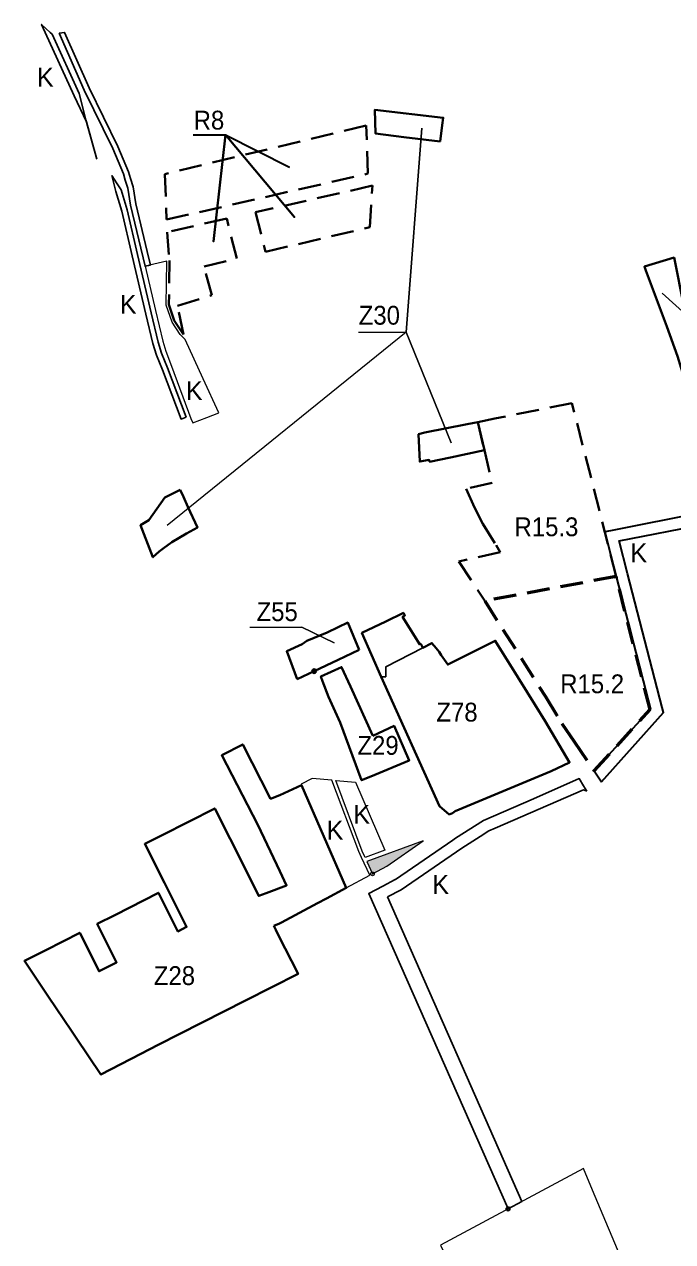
# Model space of a CAD drawing. Extents: x -650276 to -642489, y -1074311 to -1066658.
# Drawn here: x -648695 to -647869, y -1068210 to -1066658 of the extents above; entities that cross this region are included whole.
import ezdxf

# ---------------------------------------------------------------- set-up
doc = ezdxf.new("R2010")
doc.units = 0
doc.header["$LTSCALE"] = 9.6
doc.header["$PDMODE"] = 32
doc.header["$PDSIZE"] = 4.8
doc.linetypes.add('MEDIUM_DASHED', pattern=[4.5, 3, -1.5])
for name, color, linetype, lineweight in [('3', 7, 'Continuous', 40), ('4', 7, 'Continuous', 40), ('41', 7, 'Continuous', 25), ('42', 7, 'Continuous', 25), ('45', 7, 'Continuous', 40), ('46', 7, 'Continuous', 13), ('47', 7, 'Continuous', 13), ('48', 7, 'Continuous', 35), ('59', 7, 'Continuous', 13), ('61', 7, 'MEDIUM_DASHED', 40), ('62', 7, 'Continuous', 35)]:
    doc.layers.add(name, color=color, linetype=linetype, lineweight=lineweight)
doc.layers.add('43', color=7, linetype='Continuous')

msp = doc.modelspace()

# ---------------------------------------------------------------- hatches: boundary and pattern name
at = {"layer": '47'}
msp.add_hatch(color=256, dxfattribs=at).paths.add_polyline_path([(-648258.96, -1067725.37), (-648251.711, -1067741.124), (-648233.264, -1067731.288), (-648187.139, -1067699.179)])

# ---------------------------------------------------------------- linework, layer by layer
at = {"layer": '3'}
msp.add_line((-648347.51, -1067492.87), (-648326.09, -1067482.7), dxfattribs=at)
for points in [[(-648268.67, -1067455.43), (-648283.21, -1067420.88), (-648295.66, -1067426.76), (-648309.57, -1067433.34), (-648335.38, -1067444.07), (-648341.15, -1067448.14)], [(-648341.15, -1067448.14), (-648361, -1067457.36), (-648347.51, -1067492.87)], [(-648326.09, -1067482.7), (-648295.409, -1067468.129), (-648268.67, -1067455.43)]]:
    msp.add_lwpolyline(points, dxfattribs=at)
msp.add_lwpolyline([(-648251.33, -1067565.28), (-648279.86, -1067502.11), (-648291.17, -1067477.57), (-648317.435, -1067489.488), (-648315.23, -1067495.288), (-648307.57, -1067515.44), (-648292.991, -1067548.356), (-648265.601, -1067621.762), (-648254.04, -1067616.96), (-648204.88, -1067596.54), (-648224.16, -1067552.55)], close=True, dxfattribs=at)
msp.add_point((-648326.09, -1067482.7), dxfattribs=at)
at = {"layer": '4'}
msp.add_lwpolyline([(-647876.57, -1067043.5), (-647863.04, -1067081.36), (-647853.65, -1067111.91), (-647844.3, -1067141.25), (-647847.09, -1067110.58), (-647850.07, -1067077.71), (-647852.63, -1067049.52), (-647856.11, -1067011.21), (-647866.14, -1066961.98), (-647867.46, -1066955.52), (-647905.28, -1066967.07), (-647903.5, -1066972.05)], close=True, dxfattribs=at)
at = {"layer": '41'}
for points in [[(-648602.97, -1066830.11), (-648616.86, -1066779.79), (-648625.44, -1066746.45), (-648659.95, -1066670.89), (-648662.46, -1066668.53), (-648673.407, -1066658.275), (-648631.791, -1066749.394)], [(-648534.701, -1066965.077), (-648538.812, -1066947.891), (-648553.323, -1066887.238), (-648556.637, -1066865.397), (-648559.94, -1066854.66), (-648562.542, -1066846.219), (-648576.145, -1066813.802), (-648612.763, -1066739.165), (-648643.925, -1066668.483), (-648651.042, -1066669.551), (-648651.1, -1066669.56)], [(-648651.1, -1066669.56), (-648619.11, -1066742.12), (-648582.52, -1066816.7)], [(-648631.791, -1066749.394), (-648616.104, -1066782.727), (-648602.97, -1066830.11)], [(-648582.52, -1066816.7), (-648569.13, -1066848.61), (-648566.63, -1066856.72), (-648563.48, -1066866.96), (-648560.2, -1066888.58), (-648541.521, -1066966.657), (-648534.701, -1066965.077)], [(-648571.96, -1066869.37), (-648577.99, -1066860.17), (-648583.94, -1066851.11)], [(-648583.94, -1066851.11), (-648578.702, -1066871.259), (-648571.167, -1066896.326), (-648557.816, -1066953.444)], [(-648489.1, -1067158.84), (-648512.95, -1067095.97), (-648520.4, -1067077.42), (-648524.93, -1067063.35), (-648533.66, -1067026), (-648551, -1066951.85), (-648564.4, -1066894.52), (-648571.96, -1066869.37)], [(-648557.816, -1066953.444), (-648540.476, -1067027.594), (-648531.681, -1067065.222)], [(-648531.681, -1067065.222), (-648526.988, -1067079.8), (-648519.471, -1067098.516), (-648495.644, -1067161.326), (-648489.1, -1067158.84)], [(-647978.705, -1067635.817), (-647982.95, -1067628.73), (-647988.334, -1067619.747), (-648046.773, -1067645.314)], [(-648046.773, -1067645.314), (-648110.36, -1067673.133), (-648146.127, -1067695.8), (-648146.146, -1067695.813), (-648149.529, -1067698.132), (-648222.53, -1067748.178)], [(-648095.475, -1067682.994), (-647983.06, -1067633.813), (-647978.705, -1067635.817)], [(-648232.676, -1067770.513), (-648215.115, -1067761.28), (-648137.869, -1067708.325), (-648114.323, -1067693.403), (-648103.298, -1067686.416), (-648095.475, -1067682.994)], [(-648238.748, -1067756.759), (-648256.499, -1067766.091), (-648079.002, -1068168.139)], [(-648222.53, -1067748.178), (-648222.872, -1067748.412), (-648238.748, -1067756.759)], [(-648079.002, -1068168.139), (-648061.329, -1068158.649), (-648232.676, -1067770.513)]]:
    msp.add_lwpolyline(points, dxfattribs=at)
msp.add_point((-648079.002, -1068168.139), dxfattribs=at)
at = {"layer": '42'}
msp.add_lwpolyline([(-648153.98, -1067665.43), (-648149.933, -1067663.646), (-648146.21, -1067661.3), (-648023.96, -1067610.13), (-648000.63, -1067599.14), (-648031.77, -1067546.6), (-648045.04, -1067525.15), (-648076.32, -1067474.6), (-648081.31, -1067466.54), (-648095.28, -1067444.06), (-648133.56, -1067463.2), (-648150.46, -1067471.66), (-648155.85, -1067474.35), (-648164.24, -1067462.15), (-648166.97, -1067458.18), (-648170.38, -1067453.23), (-648175.94, -1067446.89), (-648187.44, -1067452.8), (-648203.39, -1067460.99), (-648234.68, -1067477.06), (-648234.87, -1067489.9), (-648240.51, -1067489.9), (-648166.173, -1067654.853)], close=True, dxfattribs=at)
at = {"layer": '45'}
for points in [[(-648165.33, -1066807.74), (-648162.8, -1066786.8), (-648161.58, -1066777.41), (-648248.77, -1066767.43), (-648247.78, -1066797.53), (-648211.58, -1066802.18)], [(-648165.33, -1066807.74), (-648162.8, -1066786.8), (-648161.58, -1066777.41), (-648248.77, -1066767.43), (-648247.78, -1066797.53), (-648211.58, -1066802.18)], [(-648185.185, -1067178.687), (-648193.02, -1067180.66), (-648191.44, -1067215.62), (-648179.42, -1067213.37), (-648179, -1067215.71), (-648152.5, -1067210.23), (-648109.1, -1067201.21), (-648117.51, -1067165.42), (-648131.01, -1067167.84)], [(-648185.185, -1067178.687), (-648193.02, -1067180.66), (-648191.44, -1067215.62), (-648179.42, -1067213.37), (-648179, -1067215.71), (-648152.5, -1067210.23), (-648109.1, -1067201.21), (-648117.51, -1067165.42), (-648131.01, -1067167.84)], [(-648496.55, -1067251.53), (-648516.47, -1067261.54), (-648536.84, -1067290.29), (-648547.17, -1067296.68), (-648531.51, -1067337.57), (-648523.55, -1067330.33), (-648518.55, -1067326.3), (-648507.25, -1067318.35), (-648488.66, -1067307.11), (-648474.69, -1067299.66), (-648486.79, -1067273.26), (-648492.62, -1067260.53)], [(-648496.55, -1067251.53), (-648516.47, -1067261.54), (-648536.84, -1067290.29), (-648547.17, -1067296.68), (-648531.51, -1067337.57), (-648523.55, -1067330.33), (-648518.55, -1067326.3), (-648507.25, -1067318.35), (-648488.66, -1067307.11), (-648474.69, -1067299.66), (-648486.79, -1067273.26), (-648492.62, -1067260.53)], [(-648153.98, -1067665.43), (-648149.933, -1067663.646), (-648146.21, -1067661.3), (-648023.96, -1067610.13), (-648000.63, -1067599.14), (-648031.77, -1067546.6), (-648045.04, -1067525.15), (-648076.32, -1067474.6), (-648081.31, -1067466.54), (-648095.28, -1067444.06), (-648133.56, -1067463.2), (-648150.46, -1067471.66), (-648155.85, -1067474.35), (-648164.24, -1067462.15), (-648166.97, -1067458.18), (-648170.38, -1067453.23), (-648175.94, -1067446.89), (-648187.44, -1067452.8), (-648190.23, -1067447.83), (-648191.46, -1067448.59), (-648213.34, -1067413.46), (-648210.48, -1067411.68), (-648212.32, -1067408.39), (-648234.808, -1067419.29), (-648265.197, -1067434.03), (-648240.51, -1067489.9), (-648166.173, -1067654.853)], [(-648153.98, -1067665.43), (-648149.933, -1067663.646), (-648146.21, -1067661.3), (-648023.96, -1067610.13), (-648000.63, -1067599.14), (-648031.77, -1067546.6), (-648045.04, -1067525.15), (-648076.32, -1067474.6), (-648081.31, -1067466.54), (-648095.28, -1067444.06), (-648133.56, -1067463.2), (-648150.46, -1067471.66), (-648155.85, -1067474.35), (-648164.24, -1067462.15), (-648166.97, -1067458.18), (-648170.38, -1067453.23), (-648175.94, -1067446.89), (-648187.44, -1067452.8), (-648190.23, -1067447.83), (-648191.46, -1067448.59), (-648213.34, -1067413.46), (-648210.48, -1067411.68), (-648212.32, -1067408.39), (-648234.808, -1067419.29), (-648265.197, -1067434.03), (-648240.51, -1067489.9), (-648166.173, -1067654.853)]]:
    msp.add_lwpolyline(points, close=True, dxfattribs=at)
at = {"layer": '45', "linetype": 'MEDIUM_DASHED', "lineweight": 53}
for points in [[(-647941.289, -1067362.104), (-648108.77, -1067393.23), (-648031.228, -1067515.162), (-648010.57, -1067549.31)], [(-648010.57, -1067549.31), (-647994.8, -1067572.37), (-647969.29, -1067609.79), (-647898.091, -1067531.72), (-647941.289, -1067362.104)]]:
    msp.add_lwpolyline(points, dxfattribs=at)
at = {"layer": '45'}
for points in [[(-648433.183, -1067696.369), (-648396.605, -1067769.277), (-648387.04, -1067765.67), (-648361.08, -1067755.88), (-648369.832, -1067737.624), (-648397.98, -1067678.79), (-648443.83, -1067589.92), (-648417.12, -1067576.17), (-648381.535, -1067645.274), (-648369.949, -1067640.851), (-648342.023, -1067628.096), (-648285.254, -1067759.008), (-648310.511, -1067772.476), (-648321.623, -1067778.399), (-648367.811, -1067802.994), (-648370.113, -1067804.22), (-648377.422, -1067807.337)], [(-648377.422, -1067807.337), (-648374.84, -1067812.43), (-648371.27, -1067819.47), (-648346.57, -1067868.56), (-648413.41, -1067902.53), (-648524.72, -1067958.93), (-648546.76, -1067970.44), (-648597.93, -1067996.72), (-648629.22, -1067950.214), (-648635.249, -1067941.252), (-648664.41, -1067897.91), (-648695.27, -1067852.04), (-648668.085, -1067838.186), (-648624.76, -1067816.11), (-648600.14, -1067865.29), (-648577.78, -1067854.07), (-648602.3, -1067804.83), (-648580.14, -1067793.61), (-648524.44, -1067765.11), (-648499.7, -1067814.37), (-648488.49, -1067808.76), (-648513.23, -1067759.38), (-648516.73, -1067752.57), (-648541.86, -1067702.86), (-648519.63, -1067691.58), (-648452.72, -1067657.62), (-648433.183, -1067696.369)]]:
    msp.add_lwpolyline(points, dxfattribs=at)
at = {"layer": '46'}
msp.add_lwpolyline([(-648269.459, -1067050.713), (-648208.812, -1067050.713), (-648188.893, -1066790.602), (-648208.812, -1067050.713), (-648151.62, -1067191.569), (-648208.812, -1067050.713), (-648513.485, -1067297.251)], dxfattribs=at)
msp.add_lwpolyline([(-648269.459, -1067050.713), (-648208.812, -1067050.713), (-648188.893, -1066790.602), (-648208.812, -1067050.713), (-648151.62, -1067191.569), (-648208.812, -1067050.713), (-648513.485, -1067297.251)], dxfattribs=at)
at = {"layer": '47'}
for points in [[(-648490.23, -1067060.06), (-648496.87, -1067053.5), (-648506.78, -1067037.81), (-648514.38, -1067016.2), (-648513.842, -1066960.243), (-648541.52, -1066966.657), (-648528.01, -1067023.13)], [(-648528.01, -1067023.13), (-648518.72, -1067061.99), (-648514.86, -1067074.83), (-648507.88, -1067093.9), (-648483.31, -1067160.63), (-648480.57, -1067166.13)], [(-648480.57, -1067166.13), (-648462.97, -1067159.24), (-648447.66, -1067153.25), (-648467.56, -1067110.02), (-648490.23, -1067060.06)], [(-648101.42, -1068344.28), (-648079.33, -1068330.03), (-647929.45, -1068244.16), (-647971.35, -1068144.48), (-647982.969, -1068116.575), (-648165.28, -1068214.465), (-648108.158, -1068330.583)]]:
    msp.add_lwpolyline(points, dxfattribs=at)
for points in [[(-648303.68, -1067621.697), (-648328.54, -1067619.51), (-648342.697, -1067626.806), (-648296.891, -1067732.172), (-648285.254, -1067759.008), (-648255.016, -1067742.886), (-648265.614, -1067720.378), (-648269.27, -1067712.6)], [(-648298.632, -1067622.141), (-648273.229, -1067624.376), (-648235.78, -1067710.79), (-648261.25, -1067720.39), (-648265.08, -1067712.06)], [(-648258.96, -1067725.37), (-648251.711, -1067741.124), (-648233.264, -1067731.288), (-648187.139, -1067699.179)]]:
    msp.add_lwpolyline(points, close=True, dxfattribs=at)
msp.add_point((-648251.711, -1067741.124), dxfattribs=at)
at = {"layer": '48'}
for points in [[(-647882.66, -1067529.231), (-647926.759, -1067358.379), (-647937.355, -1067316.774), (-647828.376, -1067295.406), (-647828.104, -1067295.352), (-647831.28, -1067280.69), (-647948.488, -1067303.671)], [(-647948.488, -1067303.671), (-647955.805, -1067305.106), (-647941.289, -1067362.104)], [(-647941.289, -1067362.104), (-647897.637, -1067531.223), (-647969.29, -1067609.79), (-647959.832, -1067623.65)], [(-647959.832, -1067623.65), (-647881.085, -1067535.333), (-647882.66, -1067529.231)]]:
    msp.add_lwpolyline(points, dxfattribs=at)
at = {"layer": '59'}
for points in [[(-647740.809, -1067055.795), (-647821.729, -1067055.795), (-647882.822, -1067000.815)], [(-648407.804, -1067426.736), (-648341.655, -1067426.736), (-648300.399, -1067446.681), (-648341.655, -1067426.736), (-648341.655, -1067426.736)]]:
    msp.add_lwpolyline(points, dxfattribs=at)
at = {"layer": '61'}
for points in [[(-648259.725, -1066787.254), (-648516.098, -1066849.061), (-648514.246, -1066907.231), (-648257.498, -1066848.545)], [(-648251.815, -1066863.877), (-648400.574, -1066897.877), (-648387.967, -1066948.136), (-648254.98, -1066916.96)], [(-648437.487, -1066905.774), (-648513.271, -1066923.097), (-648510.55, -1066959.48), (-648511.02, -1067015.58), (-648504.44, -1067035.85), (-648492.67, -1067053.5), (-648500.15, -1067017.22), (-648456.62, -1067003.59), (-648466.26, -1066967), (-648424.66, -1066956.87)]]:
    msp.add_lwpolyline(points, close=True, dxfattribs=at)
for points in [[(-647941.289, -1067362.104), (-647997.58, -1067141.08), (-648095.81, -1067160.82), (-648117.51, -1067165.42), (-648109.1, -1067201.21), (-648099.39, -1067242.54)], [(-648099.39, -1067242.54), (-648132.22, -1067250.27), (-648121.94, -1067274.29), (-648110.97, -1067294.96), (-648094.1, -1067322.05), (-648088.84, -1067331.19), (-648141.82, -1067342.88), (-648108.77, -1067393.23)]]:
    msp.add_lwpolyline(points, dxfattribs=at)
at = {"layer": '62'}
msp.add_lwpolyline([(-648480.094, -1066799.151), (-648438.938, -1066799.151), (-648454.468, -1066935.138), (-648438.938, -1066799.151), (-648351.131, -1066904.144), (-648438.938, -1066799.151), (-648357.401, -1066840.335)], dxfattribs=at)
at = {"layer": '62', "lineweight": 13}
msp.add_lwpolyline([(-648480.094, -1066799.151), (-648438.938, -1066799.151), (-648454.468, -1066935.138), (-648438.938, -1066799.151), (-648351.131, -1066904.144), (-648438.938, -1066799.151), (-648357.401, -1066840.335)], dxfattribs=at)

# ---------------------------------------------------------------- texts
at = {"layer": '43'}
for p in [(-648679.318, -1066737.684), (-648573.703, -1067027.067), (-647923.173, -1067344.01), (-648175.732, -1067766.601)]:
    msp.add_text('K', height=24, dxfattribs=at).set_placement(p)
at = {"layer": '46', "width": 0.95}
for s, p in [('Z30', (-648269.261, -1067041.062)), ('Z30', (-648269.261, -1067041.062)), ('R15.2', (-648012.511, -1067510.868)), ('Z78', (-648170.304, -1067546.968)), ('Z28', (-648530.318, -1067882.806))]:
    msp.add_text(s, height=24, dxfattribs=at).set_placement(p)
at = {"layer": '48'}
for p in [(-648489.516, -1067137.308), (-648489.516, -1067137.308), (-648276.169, -1067677.278), (-648310.251, -1067697.408)]:
    msp.add_text('K', height=24, dxfattribs=at).set_placement(p)
at = {"layer": '59', "width": 0.95}
for s, p in [('Z55', (-648399.417, -1067418.896)), ('Z29', (-648270.915, -1067589.341))]:
    msp.add_text(s, height=24, dxfattribs=at).set_placement(p)
at = {"layer": '62', "width": 0.95}
for s, p in [('R8', (-648479.548, -1066792.4)), ('R8', (-648479.548, -1066792.4)), ('R15.3', (-648070.747, -1067310.744))]:
    msp.add_text(s, height=24, dxfattribs=at).set_placement(p)

doc.saveas('drawing.dxf')
